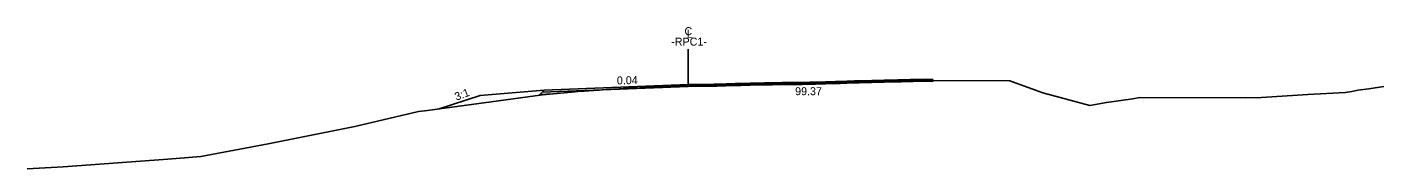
# Model space of a CAD drawing. Extents: x -313 to 385, y -480 to 1023.
# Drawn here: x -313.3 to -143.7, y -480.1 to -462.4 of the extents above; entities that cross this region are included whole.
import ezdxf

# ---------------------------------------------------------------- set-up
doc = ezdxf.new("R2010")
doc.units = 0
for name, color, linetype in [('Exist XS Center Line Elevation Label', 7, 'Continuous'), ('Exist XS Ground Line', 7, 'Continuous'), ('Prop CMT Pvmt Course 3 Wedge', 7, 'Continuous'), ('Prop CMT Pvmt Surface Overlay', 7, 'Continuous'), ('Prop CMT Shld Paved Course 1', 7, 'Continuous'), ('Prop CMT Shld Paved Course 2', 7, 'Continuous'), ('Prop CMT Slope Grass', 7, 'Continuous'), ('Prop XS Label Text', 7, 'Continuous'), ('Prop XS SE Text', 7, 'Continuous'), ('Prop XS Side Slope Text', 7, 'Continuous')]:
    doc.layers.add(name, color=color, linetype=linetype)

msp = doc.modelspace()

# ---------------------------------------------------------------- linework, layer by layer
at = {"layer": 'Exist XS Ground Line'}
msp.add_lwpolyline([(-313.26, -480.14), (-308.74, -479.88), (-295.67, -478.91), (-293.11, -478.69), (-291.57, -478.58), (-283.16, -477.01), (-272.31, -474.84), (-264.34, -472.95), (-263.23, -472.82), (-248.87, -470.85), (-244.79, -470.48), (-244.44, -470.45), (-243.65, -470.39), (-243.09, -470.35), (-241.78, -470.25), (-240.93, -470.2), (-239.28, -470.1), (-238.22, -470.04), (-237.37, -470), (-235.36, -469.91), (-232.79, -469.81), (-230.67, -469.72), (-229.79, -469.68), (-228.99, -469.66), (-227.99, -469.63), (-227.63, -469.63), (-227.06, -469.62), (-224.77, -469.58), (-224.09, -469.56), (-222.91, -469.54), (-221.13, -469.5), (-220.11, -469.48), (-218.92, -469.46), (-218.16, -469.44), (-217.11, -469.42), (-216.39, -469.41), (-215.45, -469.39), (-214.74, -469.38), (-212.24, -469.32), (-211.68, -469.31), (-210.81, -469.27), (-209.87, -469.24), (-209.27, -469.22), (-206.15, -469.15), (-204.44, -469.1), (-204.02, -469.09), (-202.93, -469.08), (-202.54, -469.06), (-200.88, -469.03), (-200.15, -469.05), (-190.45, -469.1), (-186.33, -470.61), (-180.48, -472.2), (-178.38, -471.81), (-175.09, -471.34), (-174.21, -471.19), (-161.02, -471.21), (-159.02, -471.2), (-153.23, -470.83), (-148.53, -470.55), (-147.74, -470.42), (-146.98, -470.29), (-145.59, -470.1), (-143.72, -469.83)], dxfattribs=at)
at = {"layer": 'Prop CMT Pvmt Course 3 Wedge'}
msp.add_line((-249.17, -470.79), (-249.29, -470.91), dxfattribs=at)
at = {"layer": 'Prop CMT Pvmt Surface Overlay'}
for p, q in [((-230.67, -469.56), (-248.66, -470.28)), ((-230.67, -469.56), (-227.42, -469.5)), ((-227.42, -469.5), (-227.42, -469.75)), ((-200.1, -468.92), (-200.1, -469.17)), ((-230.67, -469.81), (-248.92, -470.54)), ((-230.67, -469.81), (-227.42, -469.75))]:
    msp.add_line(p, q, dxfattribs=at)
for points in [[(-227.42, -469.5), (-227.06, -469.5), (-224.77, -469.45), (-224.09, -469.44), (-222.91, -469.41), (-221.13, -469.37), (-220.11, -469.35), (-218.92, -469.33), (-218.16, -469.32), (-217.11, -469.3), (-216.39, -469.29), (-215.45, -469.26), (-214.74, -469.25), (-212.24, -469.2), (-211.68, -469.18), (-210.81, -469.15), (-209.87, -469.11), (-209.27, -469.1), (-206.15, -469.02), (-204.44, -468.98), (-204.02, -468.96), (-202.93, -468.95), (-202.54, -468.93), (-200.88, -468.91), (-200.1, -468.92)], [(-227.42, -469.75), (-227.06, -469.75), (-224.77, -469.7), (-224.09, -469.69), (-222.91, -469.66), (-221.13, -469.62), (-220.11, -469.6), (-218.92, -469.58), (-218.16, -469.57), (-217.11, -469.55), (-216.39, -469.54), (-215.45, -469.51), (-214.74, -469.5), (-212.24, -469.45), (-211.68, -469.43), (-210.81, -469.4), (-209.87, -469.36), (-209.27, -469.35), (-206.15, -469.27), (-204.44, -469.23), (-204.02, -469.21), (-202.93, -469.2), (-202.54, -469.18), (-200.88, -469.16), (-200.1, -469.17)]]:
    msp.add_lwpolyline(points, dxfattribs=at)
at = {"layer": 'Prop CMT Shld Paved Course 1'}
msp.add_lwpolyline([(-248.66, -470.28), (-248.92, -470.54)], dxfattribs=at)
at = {"layer": 'Prop CMT Shld Paved Course 2'}
msp.add_line((-247.55, -470.73), (-249.18, -470.8), dxfattribs=at)
msp.add_lwpolyline([(-248.91, -470.53), (-249.18, -470.8)], dxfattribs=at)
at = {"layer": 'Prop CMT Slope Grass'}
for p, q in [((-256.66, -470.92), (-261.76, -472.62)), ((-248.66, -470.28), (-256.66, -470.92))]:
    msp.add_line(p, q, dxfattribs=at)
at = {"layer": 'Prop XS Label Text'}
msp.add_line((-230.67, -469.56), (-230.67, -465.12), dxfattribs=at)

# ---------------------------------------------------------------- texts
at = {"layer": 'Exist XS Center Line Elevation Label'}
msp.add_text('99.37', height=1, dxfattribs=at).set_placement((-217.29, -470.9))
at = {"layer": 'Prop XS Label Text'}
for s, p in [('C', (-231.12, -463.38)), ('L', (-230.84, -463.71)), ('-RPC1-', (-232.77, -464.69))]:
    msp.add_text(s, height=1, dxfattribs=at).set_placement(p)
at = {"layer": 'Prop XS SE Text'}
msp.add_text('0.04', height=1, rotation=0.8783, dxfattribs=at).set_placement((-239.56, -469.55))
at = {"layer": 'Prop XS Side Slope Text'}
msp.add_text('3:1', height=1, rotation=20.6597, dxfattribs=at).set_placement((-259.62, -471.6))

doc.saveas('drawing.dxf')
